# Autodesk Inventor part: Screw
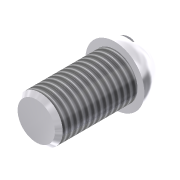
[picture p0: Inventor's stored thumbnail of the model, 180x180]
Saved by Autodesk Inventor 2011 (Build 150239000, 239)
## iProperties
Shininess: 77.0
Length Units: 11269
Angle Units: 11279
Time Units: 11290
Mass Units: 11283
Length Display Precision: 3
Angle Display Precision: 2
Created: 2002-01
Part Number: Screw
Document SubType Name: Modeling
Designer: ***
Density: 1 g/cm^3
Density: 0.0
Volumn: 0.0
Area: 0.0
PropertySet Name: Model Information
Control State: 0
Master: False
Checked Out: False
Author: ***
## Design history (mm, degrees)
sketch "Sketch1"
  geometry: L1 (-0.061, 13.328)-(-0.061, -1.672); L2 (-0.061, -1.672)-(14.939, -1.672); A1 r 15 centre (-0.061, -1.672) between (14.939, -1.672) and (-0.061, 13.328)
  constraints: 4 end point, 2 point on circle, 1 centre point
  dimensions: "d0" = 15 radius of A1
revolve "Revolution1" sketch "Sketch1" stored, may be unused: angle "d3" = 90 deg
workplane "Work Plane2"
sketch "Sketch3"
  geometry: L1 (-3, 26)-(3, 26); L2 (3, 26)-(3, 6); L3 (3, 6)-(-3, 6); L4 (-3, 6)-(-3, 26); L5 (-15, 0)-(15, 0) reference
  constraints: 8 end point, 2 parallel, 1 horizontal, 1 perpendicular
  dimensions: "d11" = 6 distance of L1.start L1.end; "d12" = 20 distance of L3.end L1.start; "d13" = 6 distance between parallel lines of L5 L3; "d14" = 12 distance from line of L4 L5.start
extrude "Extrusion2" cut sketch "Sketch3" stored distance "d15" = 10; taper "d16" = 0 deg
sketch "Sketch4"
  geometry: C1 r 11.5 at (0, 0); C2 r 15 at (0, 0) reference
  constraints: 1 centre point, 1 concentric
  dimensions: "d17" = 23 diameter of C1
extrude "Extrusion3" join sketch "Sketch4" distance "d18" = 40; taper "d19" = 0 deg
chamfer "Chamfer1" distance "d20" = 2; stored, may be unused: second distance "d21" = 2, angle "d24" = 45 deg
thread "Thread1" dims "d22" = 10, "d23" = 0
body "Solid1"
